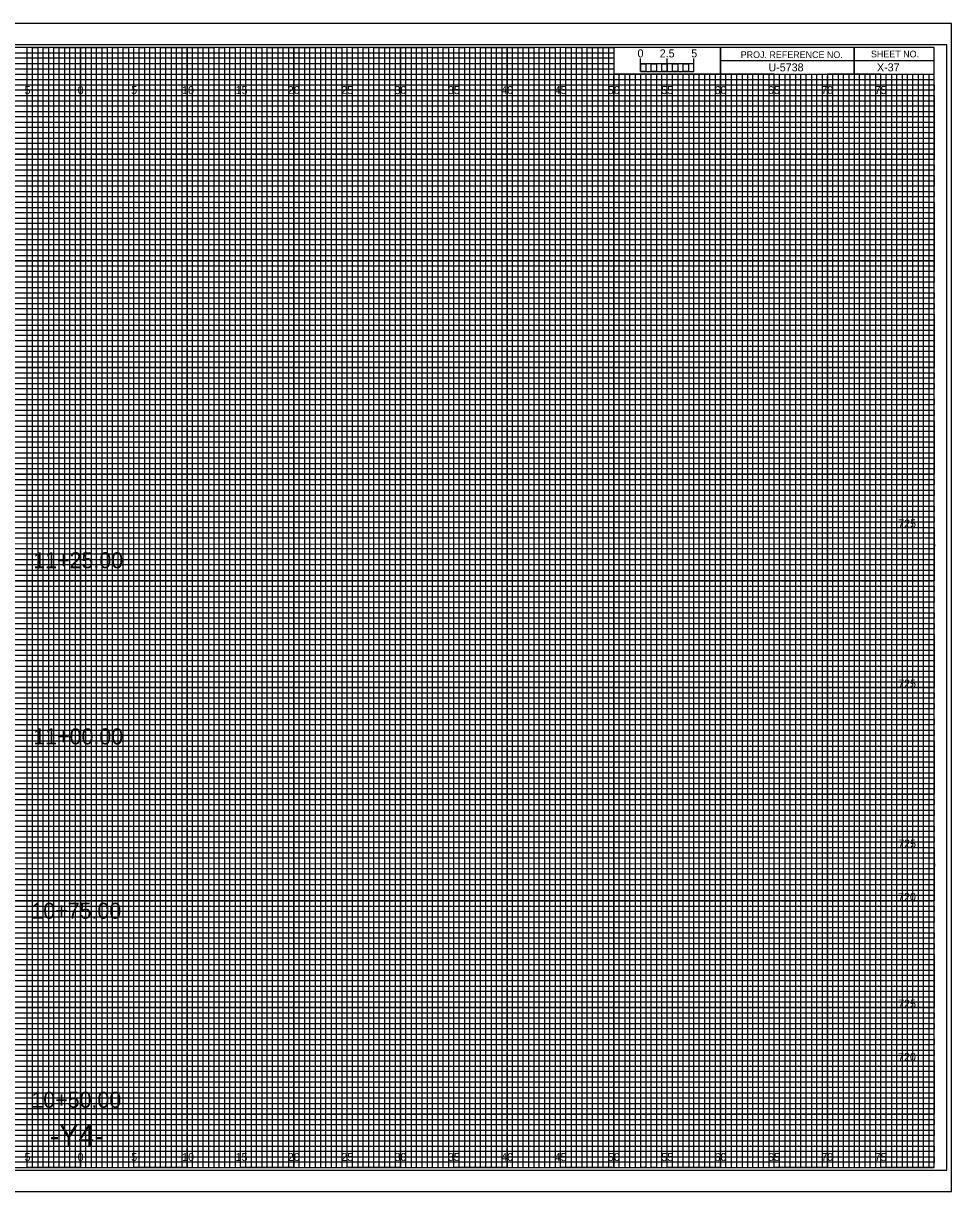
# Model space of a CAD drawing. Extents: x -7 to 162, y -2 to 107.
# Drawn here: x 74.6 to 161.7, y -2.3 to 107.3 of the extents above; entities that cross this region are included whole.
import ezdxf

# ---------------------------------------------------------------- set-up
doc = ezdxf.new("R2010")
doc.units = 0
for name, color, linetype in [('Exist XS Center Line Elevation Label', 7, 'Continuous'), ('Prop CMT Pvmt Course 1', 7, 'Continuous'), ('Prop CMT Pvmt Course 2', 7, 'Continuous'), ('Prop CMT Pvmt Course 3', 7, 'Continuous'), ('Prop CMT Pvmt Surface', 7, 'Continuous'), ('Prop CMT Pvmt Surface Shoulder', 7, 'Continuous'), ('Prop CMT Shld Paved Course 1', 7, 'Continuous'), ('Prop CMT Shld Paved Course 2', 7, 'Continuous'), ('Prop CMT Shld Paved Course 3', 7, 'Continuous'), ('Prop CMT Subgrade Earthwork', 7, 'Continuous'), ('Prop XS Alignment Label', 7, 'Continuous'), ('Prop XS Bar Scale Labels', 7, 'Continuous'), ('Prop XS Project Number', 7, 'Continuous'), ('Prop XS SE Text', 7, 'Continuous'), ('Prop XS Sheet Number', 7, 'Continuous'), ('Prop XS Station Labels', 7, 'Continuous'), ('Scratch_Level_5', 7, 'Continuous')]:
    doc.layers.add(name, color=color, linetype=linetype)

msp = doc.modelspace()

# ---------------------------------------------------------------- linework, layer by layer
at = {"layer": 'Prop CMT Pvmt Course 1'}
msp.add_lwpolyline([(-6.7, -2.25), (161.65, -2.25), (161.65, 107.25), (-6.7, 107.25)], close=True, dxfattribs=at)
at = {"layer": 'Prop CMT Pvmt Course 2'}
msp.add_lwpolyline([(-5.4, -0.25), (161.2, -0.25), (161.2, 105.25), (-5.4, 105.25)], close=True, dxfattribs=at)
at = {"layer": 'Prop CMT Pvmt Course 3'}
for p, q in [((75, 0), (75, 105)), ((80, 0), (80, 105)), ((85, 0), (85, 105)), ((90, 0), (90, 105)), ((95, 0), (95, 105)), ((100, 0), (100, 105)), ((105, 0), (105, 105)), ((110, 0), (110, 105)), ((115, 0), (115, 105)), ((120, 0), (120, 105)), ((125, 0), (125, 105)), ((130, 0), (130, 102.34)), ((135, 0), (135, 102.34)), ((140, 0), (140, 102.34)), ((145, 0), (145, 102.34)), ((150, 0), (150, 102.34)), ((155, 0), (155, 102.34)), ((0, 100), (160, 100)), ((0, 95), (160, 95)), ((0, 90), (160, 90)), ((0, 85), (160, 85)), ((0, 80), (160, 80)), ((0, 75), (160, 75)), ((0, 70), (160, 70)), ((0, 65), (160, 65)), ((0, 60), (160, 60)), ((0, 55), (160, 55)), ((0, 50), (160, 50)), ((0, 45), (160, 45)), ((0, 40), (160, 40)), ((0, 35), (160, 35)), ((0, 30), (160, 30)), ((0, 25), (160, 25)), ((0, 20), (160, 20)), ((0, 15), (160, 15)), ((0, 10), (160, 10)), ((0, 5), (160, 5))]:
    msp.add_line(p, q, dxfattribs=at)
at = {"layer": 'Prop CMT Pvmt Surface'}
for p, q in [((133.5, 102.5), (133, 102.5)), ((133, 102.5), (133, 0)), ((133.5, 0), (133.5, 102.5)), ((134.5, 102.5), (134, 102.5)), ((134, 102.5), (134, 0)), ((134.5, 0), (134.5, 102.5)), ((133, 0), (132.5, 0)), ((134, 0), (133.5, 0))]:
    msp.add_line(p, q, dxfattribs=at)
for points in [[(75, 0), (75.5, 0), (75.5, 105), (76, 105), (76, 0)], [(76, 0), (76.5, 0), (76.5, 105), (77, 105), (77, 0)], [(77.5, 0), (78, 0), (78, 105), (78.5, 105), (78.5, 0)], [(78.5, 0), (79, 0), (79, 105), (79.5, 105), (79.5, 0)], [(80, 0), (80.5, 0), (80.5, 105), (81, 105), (81, 0)], [(81, 0), (81.5, 0), (81.5, 105), (82, 105), (82, 0)], [(82.5, 0), (83, 0), (83, 105), (83.5, 105), (83.5, 0)], [(83.5, 0), (84, 0), (84, 105), (84.5, 105), (84.5, 0)], [(85, 0), (85.5, 0), (85.5, 105), (86, 105), (86, 0)], [(86, 0), (86.5, 0), (86.5, 105), (87, 105), (87, 0)], [(87.5, 0), (88, 0), (88, 105), (88.5, 105), (88.5, 0)], [(88.5, 0), (89, 0), (89, 105), (89.5, 105), (89.5, 0)], [(90, 0), (90.5, 0), (90.5, 105), (91, 105), (91, 0)], [(91, 0), (91.5, 0), (91.5, 105), (92, 105), (92, 0)], [(92.5, 0), (93, 0), (93, 105), (93.5, 105), (93.5, 0)], [(93.5, 0), (94, 0), (94, 105), (94.5, 105), (94.5, 0)], [(95, 0), (95.5, 0), (95.5, 105), (96, 105), (96, 0)], [(96, 0), (96.5, 0), (96.5, 105), (97, 105), (97, 0)], [(97.5, 0), (98, 0), (98, 105), (98.5, 105), (98.5, 0)], [(98.5, 0), (99, 0), (99, 105), (99.5, 105), (99.5, 0)], [(100, 0), (100.5, 0), (100.5, 105), (101, 105), (101, 0)], [(101, 0), (101.5, 0), (101.5, 105), (102, 105), (102, 0)], [(102.5, 0), (103, 0), (103, 105), (103.5, 105), (103.5, 0)], [(103.5, 0), (104, 0), (104, 105), (104.5, 105), (104.5, 0)], [(105, 0), (105.5, 0), (105.5, 105), (106, 105), (106, 0)], [(106, 0), (106.5, 0), (106.5, 105), (107, 105), (107, 0)], [(107.5, 0), (108, 0), (108, 105), (108.5, 105), (108.5, 0)], [(108.5, 0), (109, 0), (109, 105), (109.5, 105), (109.5, 0)], [(110, 0), (110.5, 0), (110.5, 105), (111, 105), (111, 0)], [(111, 0), (111.5, 0), (111.5, 105), (112, 105), (112, 0)], [(112.5, 0), (113, 0), (113, 105), (113.5, 105), (113.5, 0)], [(113.5, 0), (114, 0), (114, 105), (114.5, 105), (114.5, 0)], [(115, 0), (115.5, 0), (115.5, 105), (116, 105), (116, 0)], [(116, 0), (116.5, 0), (116.5, 105), (117, 105), (117, 0)], [(117.5, 0), (118, 0), (118, 105), (118.5, 105), (118.5, 0)], [(118.5, 0), (119, 0), (119, 105), (119.5, 105), (119.5, 0)], [(120, 0), (120.5, 0), (120.5, 105), (121, 105), (121, 0)], [(121, 0), (121.5, 0), (121.5, 105), (122, 105), (122, 0)], [(122.5, 0), (123, 0), (123, 105), (123.5, 105), (123.5, 0)], [(123.5, 0), (124, 0), (124, 105), (124.5, 105), (124.5, 0)], [(125, 0), (125.5, 0), (125.5, 105), (126, 105), (126, 0)], [(126, 0), (126.5, 0), (126.5, 105), (127, 105), (127, 0)], [(127.5, 0), (128, 0), (128, 105), (128.5, 105), (128.5, 0)], [(128.5, 0), (129, 0), (129, 105), (129.5, 105), (129.5, 0)], [(130, 0), (130.5, 0), (130.5, 102.5), (131.01, 102.5), (131.01, 0)], [(131, 0), (131.5, 0), (131.5, 102.5), (132, 102.5), (132, 0)], [(135, 0), (135.49, 0), (135.49, 102.5), (136, 102.5), (136, 0)], [(136, 0), (136.5, 0), (136.5, 102.5), (137.03, 102.5), (137.03, 0)], [(137.5, 0), (138, 0), (138, 102.5), (138.5, 102.5), (138.5, 0)], [(138.5, 0), (139, 0), (139, 102.5), (139.5, 102.5), (139.5, 0)], [(140, 0), (140.5, 0), (140.5, 102.5), (141, 102.5), (141, 0)], [(141, 0), (141.5, 0), (141.5, 102.5), (142, 102.5), (142, 0)], [(142.5, 0), (143, 0), (143, 102.5), (143.5, 102.5), (143.5, 0)], [(143.5, 0), (144, 0), (144, 102.5), (144.5, 102.5), (144.5, 0)], [(145, 0), (145.5, 0), (145.5, 102.5), (146, 102.5), (146, 0)], [(146, 0), (146.5, 0), (146.5, 102.5), (147, 102.5), (147, 0)], [(147.5, 0), (148, 0), (148, 102.5), (148.5, 102.5), (148.5, 0)], [(148.5, 0), (149, 0), (149, 102.5), (149.5, 102.5), (149.5, 0)], [(150, 0), (150.5, 0), (150.5, 102.5), (151, 102.5), (151, 0)], [(151, 0), (151.5, 0), (151.5, 102.5), (152, 102.5), (152, 0)], [(152.5, 0), (153, 0), (153, 102.5), (153.5, 102.5), (153.5, 0)], [(153.5, 0), (154, 0), (154, 102.5), (154.5, 102.5), (154.5, 0)], [(155, 0), (155.5, 0), (155.5, 102.5), (156, 102.5), (156, 0)], [(156, 0), (156.5, 0), (156.5, 102.5), (157, 102.5), (157, 0)], [(157.5, 0), (158, 0), (158, 102.5), (158.5, 102.5), (158.5, 0)], [(158.5, 0), (159, 0), (159, 102.5), (159.5, 102.5), (159.5, 0)]]:
    msp.add_lwpolyline(points, dxfattribs=at)
at = {"layer": 'Prop CMT Pvmt Surface Shoulder'}
for p, q in [((132.5, 102.75), (132.5, 103.95)), ((132.5, 103.45), (132.5, 103.95)), ((135, 102.75), (135, 103.95)), ((137.5, 102.75), (137.5, 103.95)), ((137.5, 103.45), (137.5, 103.95))]:
    msp.add_line(p, q, dxfattribs=at)
for points in [[(137.5, 103.45), (132.5, 103.45), (132.5, 102.75), (137.5, 102.75)], [(132.5, 103.45), (133, 103.45), (133, 102.75), (132.5, 102.75)], [(133.5, 103.45), (134, 103.45), (134, 102.75), (133.5, 102.75)], [(134.5, 103.45), (135, 103.45), (135, 102.75), (134.5, 102.75)], [(135.5, 103.45), (136, 103.45), (136, 102.75), (135.5, 102.75)], [(136.5, 103.45), (137, 103.45), (137, 102.75), (136.5, 102.75)]]:
    msp.add_lwpolyline(points, close=True, dxfattribs=at)
at = {"layer": 'Prop CMT Shld Paved Course 1'}
for p, q in [((75, 105), (70, 105)), ((75, 0), (75, 105)), ((85, 105), (80, 105)), ((80, 105), (80, 0)), ((85, 0), (85, 105)), ((95, 105), (90, 105)), ((90, 105), (90, 0)), ((95, 0), (95, 105)), ((105, 105), (100, 105)), ((100, 105), (100, 0)), ((105, 0), (105, 105)), ((115, 105), (110, 105)), ((110, 105), (110, 0)), ((115, 0), (115, 105)), ((125, 105), (120, 105)), ((120, 105), (120, 0)), ((125, 0), (125, 105)), ((130, 105), (130, 0)), ((135, 0), (135, 102.5)), ((145, 102.5), (140, 102.5)), ((140, 102.5), (140, 0)), ((145, 0), (145, 102.5)), ((155, 102.5), (150, 102.5)), ((150, 102.5), (150, 0)), ((155, 0), (155, 102.5)), ((80, 0), (75, 0)), ((90, 0), (85, 0)), ((100, 0), (95, 0)), ((110, 0), (105, 0)), ((120, 0), (115, 0)), ((130, 0), (125, 0)), ((140, 0), (135, 0)), ((150, 0), (145, 0)), ((160, 0), (155, 0)), ((160, 0), (160, 0))]:
    msp.add_line(p, q, dxfattribs=at)
for points in [[(0, 100), (160, 100), (160, 95), (0, 95)], [(0, 90), (160, 90), (160, 85), (0, 85)], [(0, 80), (160, 80), (160, 75), (0, 75)], [(0, 70), (160, 70), (160, 65), (0, 65)], [(0, 60), (160, 60), (160, 55), (0, 55)], [(0, 50), (160, 50), (160, 45), (0, 45)], [(0, 40), (160, 40), (160, 35), (0, 35)], [(0, 30), (160, 30), (160, 25), (0, 25)], [(0, 20), (160, 20), (160, 15), (0, 15)], [(0, 10), (160, 10), (160, 5), (0, 5)]]:
    msp.add_lwpolyline(points, dxfattribs=at)
at = {"layer": 'Prop CMT Shld Paved Course 2'}
for points in [[(72.5, 0), (77.5, 0), (77.5, 105), (82.5, 105), (82.5, 0), (87.5, 0), (87.5, 105), (92.5, 105), (92.5, 0), (97.5, 0), (97.5, 105), (102.5, 105), (102.5, 0), (107.5, 0), (107.5, 105), (112.5, 105), (112.5, 0), (117.5, 0), (117.5, 105), (122.5, 105), (122.5, 0), (127.5, 0), (127.5, 105), (129.97, 105), (130, 105), (130, 102.5), (132.5, 102.5), (132.5, 0), (137.5, 0), (137.5, 102.5), (142.5, 102.5), (142.5, 0), (147.5, 0), (147.5, 102.5), (152.5, 102.5), (152.5, 0), (157.5, 0), (157.5, 102.5)], [(0, 102.5), (137.5, 102.5)], [(0, 92.5), (160, 92.5), (160, 97.5), (0, 97.5)], [(0, 82.5), (160, 82.5), (160, 87.5), (0, 87.5)], [(0, 72.5), (160, 72.5), (160, 77.5), (0, 77.5)], [(0, 62.5), (160, 62.5), (160, 67.5), (0, 67.5)], [(0, 52.5), (160, 52.5), (160, 57.5), (0, 57.5)], [(0, 42.5), (160, 42.5), (160, 47.5), (0, 47.5)], [(0, 32.5), (160, 32.5), (160, 37.5), (0, 37.5)], [(0, 22.5), (160, 22.5), (160, 27.5), (0, 27.5)], [(0, 12.5), (160, 12.5), (160, 17.5), (0, 17.5)], [(0, 2.5), (160, 2.5), (160, 7.5), (0, 7.5)]]:
    msp.add_lwpolyline(points, dxfattribs=at)
at = {"layer": 'Prop CMT Shld Paved Course 3'}
for p, q in [((0, 104.5), (130, 104.5)), ((130, 104.5), (130, 103.99)), ((130, 103.99), (0, 103.99)), ((0, 103.5), (130, 103.5)), ((130, 102.95), (0, 102.95)), ((130, 103.5), (130, 102.95)), ((0, 102), (160, 102))]:
    msp.add_line(p, q, dxfattribs=at)
for points in [[(0, 101.5), (135, 101.5), (160, 101.5), (160, 101), (0, 101)], [(0, 100.5), (160, 100.5), (160, 99.5), (0, 99.5)], [(0, 99), (160, 99), (160, 98.5), (0, 98.49)], [(0, 98), (160, 98), (160, 97), (0, 97)], [(0, 96.5), (160, 96.5), (160, 96), (0, 96)], [(0, 95.5), (160, 95.5), (160, 94.5), (0, 94.5)], [(0, 94), (160, 94), (160, 93.5), (0, 93.5)], [(0, 93), (160, 93), (160, 92), (0, 92)], [(0, 91.5), (160, 91.5), (160, 91), (0, 91)], [(0, 90.5), (160, 90.5), (160, 89.5), (0, 89.5)], [(0, 89), (160, 89), (160, 88.5), (0, 88.5)], [(0, 88), (160, 88), (160, 86.98), (160, 86.5), (160, 86), (0, 86)], [(0, 87), (160, 87), (160, 86.5), (0, 86.5)], [(0, 85.5), (160, 85.5), (160, 84.5), (0, 84.52)], [(0, 84.52), (160, 84.5), (160, 84), (0, 84)], [(0, 83.5), (160, 83.5), (160, 83), (0, 83)], [(0, 82), (160, 82), (160, 81.5), (0, 81.5)], [(0, 81), (160, 81), (160, 80.5), (0, 80.5)], [(-0.04, 79.45), (160, 79.45), (160, 78.94), (-0.04, 78.94)], [(0, 78.5), (160, 78.5), (160, 78), (0, 78)], [(0, 77), (160, 77), (160, 76.5), (0, 76.5)], [(0, 76), (160, 76), (160, 75.5), (0, 75.5)], [(0, 74.5), (160, 74.5), (160, 74), (0, 74)], [(0, 73.5), (160, 73.5), (160, 73), (0, 73)], [(0, 72), (160, 72), (160, 71.5), (0, 71.5)], [(0, 71), (160, 71), (160, 70.5), (0, 70.5)], [(0, 69.5), (160, 69.5), (160, 68.99), (0, 69)], [(0, 68.5), (160, 68.5), (160, 68), (0, 68)], [(0, 67), (160, 67), (160, 66.5), (0, 66.5)], [(0, 66), (160, 66), (160, 65.5), (0, 65.5)], [(0, 64.5), (160, 64.5), (160, 64), (0, 64)], [(0, 63.5), (160, 63.5), (160, 63), (0, 63)], [(0, 62), (160, 62), (160, 61.5), (0, 61.5)], [(0, 61), (160, 61), (160, 60.5), (0, 60.5)], [(0, 59.5), (160, 59.5), (160, 59), (0, 59)], [(0, 58.5), (160.03, 58.45), (160, 58), (0, 58)], [(0, 57), (160, 57), (160, 56.5), (0, 56.5)], [(0, 56), (160, 56), (160, 55.5), (0, 55.5)], [(0, 54.5), (160, 54.5), (160, 54), (0, 54)], [(0, 53.5), (160, 53.5), (160, 53), (0, 53)], [(0, 52), (160, 52), (160, 51.5), (0, 51.5)], [(0, 51), (160, 51), (160, 50.5), (0, 50.5)], [(0, 49.5), (160, 49.5), (160, 49), (0, 49)], [(0, 48.5), (160, 48.5), (160, 48), (0, 48)], [(0, 47), (160, 47), (160, 46.5), (0, 46.5)], [(0, 46), (160, 46), (160, 45.5), (0, 45.5)], [(0, 44.5), (160, 44.5), (160, 44), (0, 44)], [(0, 43.5), (160, 43.5), (160, 43), (0, 43)], [(0, 42), (160, 42), (160, 41.5), (0, 41.5)], [(0, 41), (160, 41), (160, 40.5), (0, 40.5)], [(0, 39.5), (160, 39.5), (160, 38.99), (0, 39)], [(0, 38.5), (160, 38.5), (160, 38), (0, 38)], [(0, 37), (160, 37), (160, 36.5), (0, 36.5)], [(0, 36), (160, 36), (160, 35.5), (0, 35.5)], [(0, 34.5), (160, 34.5), (160, 34), (0, 34)], [(0, 33.5), (160, 33.5), (160, 33), (0, 33)], [(0, 32), (160, 32), (160, 31.5), (0, 31.5)], [(0, 31), (160, 31), (160, 30.5), (0, 30.5)], [(0, 29.5), (160, 29.5), (160, 29), (0, 29)], [(0, 28.5), (160.03, 28.46), (160, 28), (0, 28)], [(0, 27), (160, 27), (160, 26.5), (0, 26.5)], [(0, 26), (160, 26), (160, 25.5), (0, 25.5)], [(0, 24.5), (160, 24.5), (160, 24), (0, 24)], [(0, 23.5), (160, 23.5), (160, 23), (0, 23)], [(0, 22), (160, 22), (160, 21.5), (0, 21.5)], [(0, 21), (160, 21), (160, 20.5), (0, 20.5)], [(0, 19.5), (160, 19.5), (160, 19), (0, 19)], [(0, 18.5), (160, 18.5), (160, 18), (0, 18)], [(0, 17), (160, 17), (160, 16.5), (0, 16.5)], [(0, 16), (160, 16), (160, 15.5), (0, 15.5)], [(0, 14.5), (160, 14.5), (160, 14), (0, 14)], [(0, 13.5), (160, 13.5), (160, 13), (0, 13)], [(0, 12), (160, 12), (160, 11.5), (0, 11.5)], [(0, 11), (160, 11), (160, 10.5), (0, 10.5)], [(0, 9.5), (160, 9.5), (160, 9), (0, 9)], [(0, 8.5), (160, 8.5), (160, 8), (0, 8)], [(0, 7), (160, 7), (160, 6.5), (0, 6.5)], [(0, 6), (160, 6), (160, 5.5), (0, 5.5)], [(0, 4.5), (160, 4.5), (160, 4), (0, 4)], [(0, 3.5), (160, 3.5), (160, 3), (0, 3)], [(0, 2), (160, 2), (160, 1.5), (0, 1.5)], [(0, 1), (160, 1), (160, 0.5), (0, 0.5)]]:
    msp.add_lwpolyline(points, dxfattribs=at)
at = {"layer": 'Prop CMT Subgrade Earthwork'}
for p, q in [((152.5, 105), (152.5, 102.5)), ((152.5, 102.5), (152.5, 105)), ((160, 103.75), (140, 103.75)), ((140, 103.75), (140, 102.5)), ((140, 102.5), (160, 102.5))]:
    msp.add_line(p, q, dxfattribs=at)
for points in [[(160, 105), (0, 105), (0, 0), (160, 0)], [(140, 105), (130, 105), (130, 102.52), (140, 102.52)], [(160, 105), (140, 105), (140, 102.5), (160, 102.5)]]:
    msp.add_lwpolyline(points, close=True, dxfattribs=at)
at = {"layer": 'Prop XS SE Text'}
for p, q in [((161.65, 107.25), (-6.7, 107.25)), ((-6.7, -2.25), (161.65, -2.25))]:
    msp.add_line(p, q, dxfattribs=at)

# ---------------------------------------------------------------- texts
at = {"layer": 'Exist XS Center Line Elevation Label'}
for s, p in [('5', (74.74, 100.62)), ('0', (79.73, 100.62)), ('0', (79.73, 100.62)), ('5', (84.74, 100.62)), ('10', (89.52, 100.62)), ('15', (94.53, 100.62)), ('20', (99.43, 100.62)), ('25', (104.44, 100.62)), ('30', (109.43, 100.62)), ('35', (114.44, 100.62)), ('40', (119.43, 100.62)), ('45', (124.44, 100.62)), ('50', (129.43, 100.62)), ('55', (134.44, 100.62)), ('60', (139.43, 100.62)), ('65', (144.44, 100.62)), ('70', (149.43, 100.62)), ('75', (154.44, 100.62)), ('5', (74.74, 0.62)), ('0', (79.73, 0.62)), ('0', (79.73, 0.62)), ('5', (84.74, 0.62)), ('10', (89.52, 0.62)), ('15', (94.53, 0.62)), ('20', (99.43, 0.62)), ('25', (104.44, 0.62)), ('30', (109.43, 0.62)), ('35', (114.44, 0.62)), ('40', (119.43, 0.62)), ('45', (124.44, 0.62)), ('50', (129.43, 0.62)), ('55', (134.44, 0.62)), ('60', (139.43, 0.62)), ('65', (144.44, 0.62)), ('70', (149.43, 0.62)), ('75', (154.44, 0.62))]:
    msp.add_text(s, height=0.75, dxfattribs=at).set_placement(p)
at = {"layer": 'Prop CMT Pvmt Surface Shoulder'}
msp.add_text('0', height=0.75, dxfattribs=at).set_placement((132.21, 104.06))
at = {"layer": 'Prop CMT Subgrade Earthwork'}
for s, p in [('PROJ. REFERENCE NO.', (141.88, 104)), ('SHEET NO.', (154.09, 104.06))]:
    msp.add_text(s, height=0.625, dxfattribs=at).set_placement(p)
at = {"layer": 'Prop XS Alignment Label'}
msp.add_text('-Y4-', height=2, dxfattribs=at).set_placement((77.12, 2))
at = {"layer": 'Prop XS Bar Scale Labels'}
for s, p in [('2.5', (134.29, 104.06)), ('5', (137.24, 104.06))]:
    msp.add_text(s, height=0.75, dxfattribs=at).set_placement(p)
at = {"layer": 'Prop XS Project Number'}
msp.add_text('U-5738', height=0.75, dxfattribs=at).set_placement((144.48, 102.75))
at = {"layer": 'Prop XS Sheet Number'}
msp.add_text('X-37', height=0.75, dxfattribs=at).set_placement((154.65, 102.75))
at = {"layer": 'Prop XS Station Labels'}
for s, p in [('11+25.00', (75.57, 56.18)), ('11+00.00', (75.57, 39.67)), ('10+75.00', (75.39, 23.33)), ('10+50.00', (75.39, 5.61))]:
    msp.add_text(s, height=1.5, dxfattribs=at).set_placement(p)
at = {"layer": 'Scratch_Level_5'}
for s, p in [('725', (156.64, 60)), ('725', (156.64, 45)), ('725', (156.64, 30)), ('720', (156.63, 25)), ('725', (156.64, 15)), ('720', (156.63, 10))]:
    msp.add_text(s, height=0.75, dxfattribs=at).set_placement(p)

doc.saveas('drawing.dxf')
